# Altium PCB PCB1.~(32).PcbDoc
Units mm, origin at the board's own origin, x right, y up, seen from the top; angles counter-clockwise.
Board outline 145.29 x 144.91 mm, 2 copper layers (Top Layer, Bottom Layer); 37 components, 35 nets, 209 pads, 0 vias.
Unrouted connection lines stored in the file: 9.
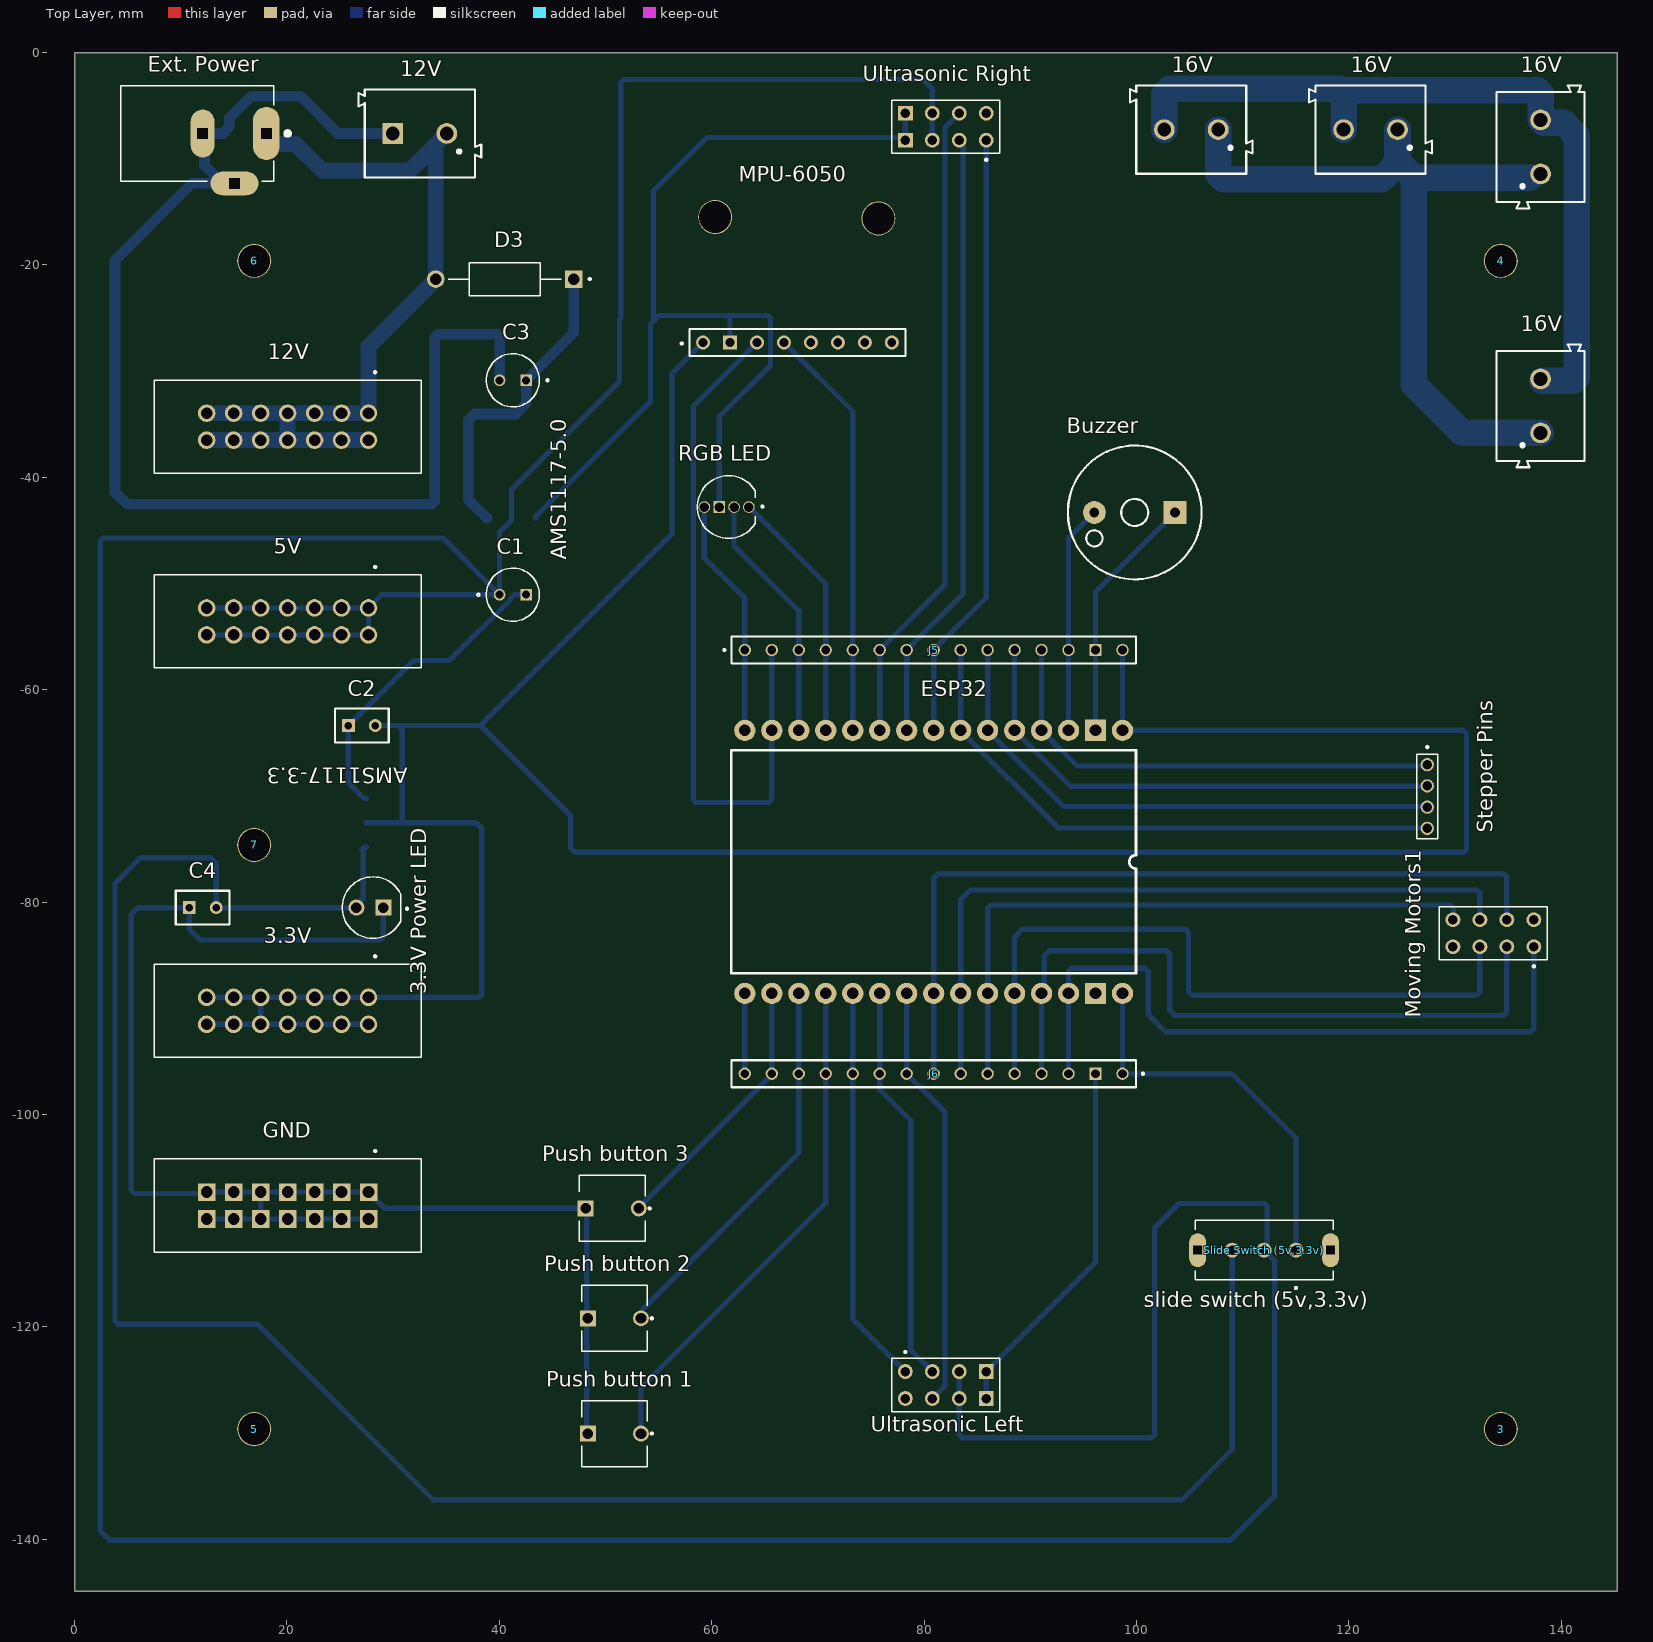
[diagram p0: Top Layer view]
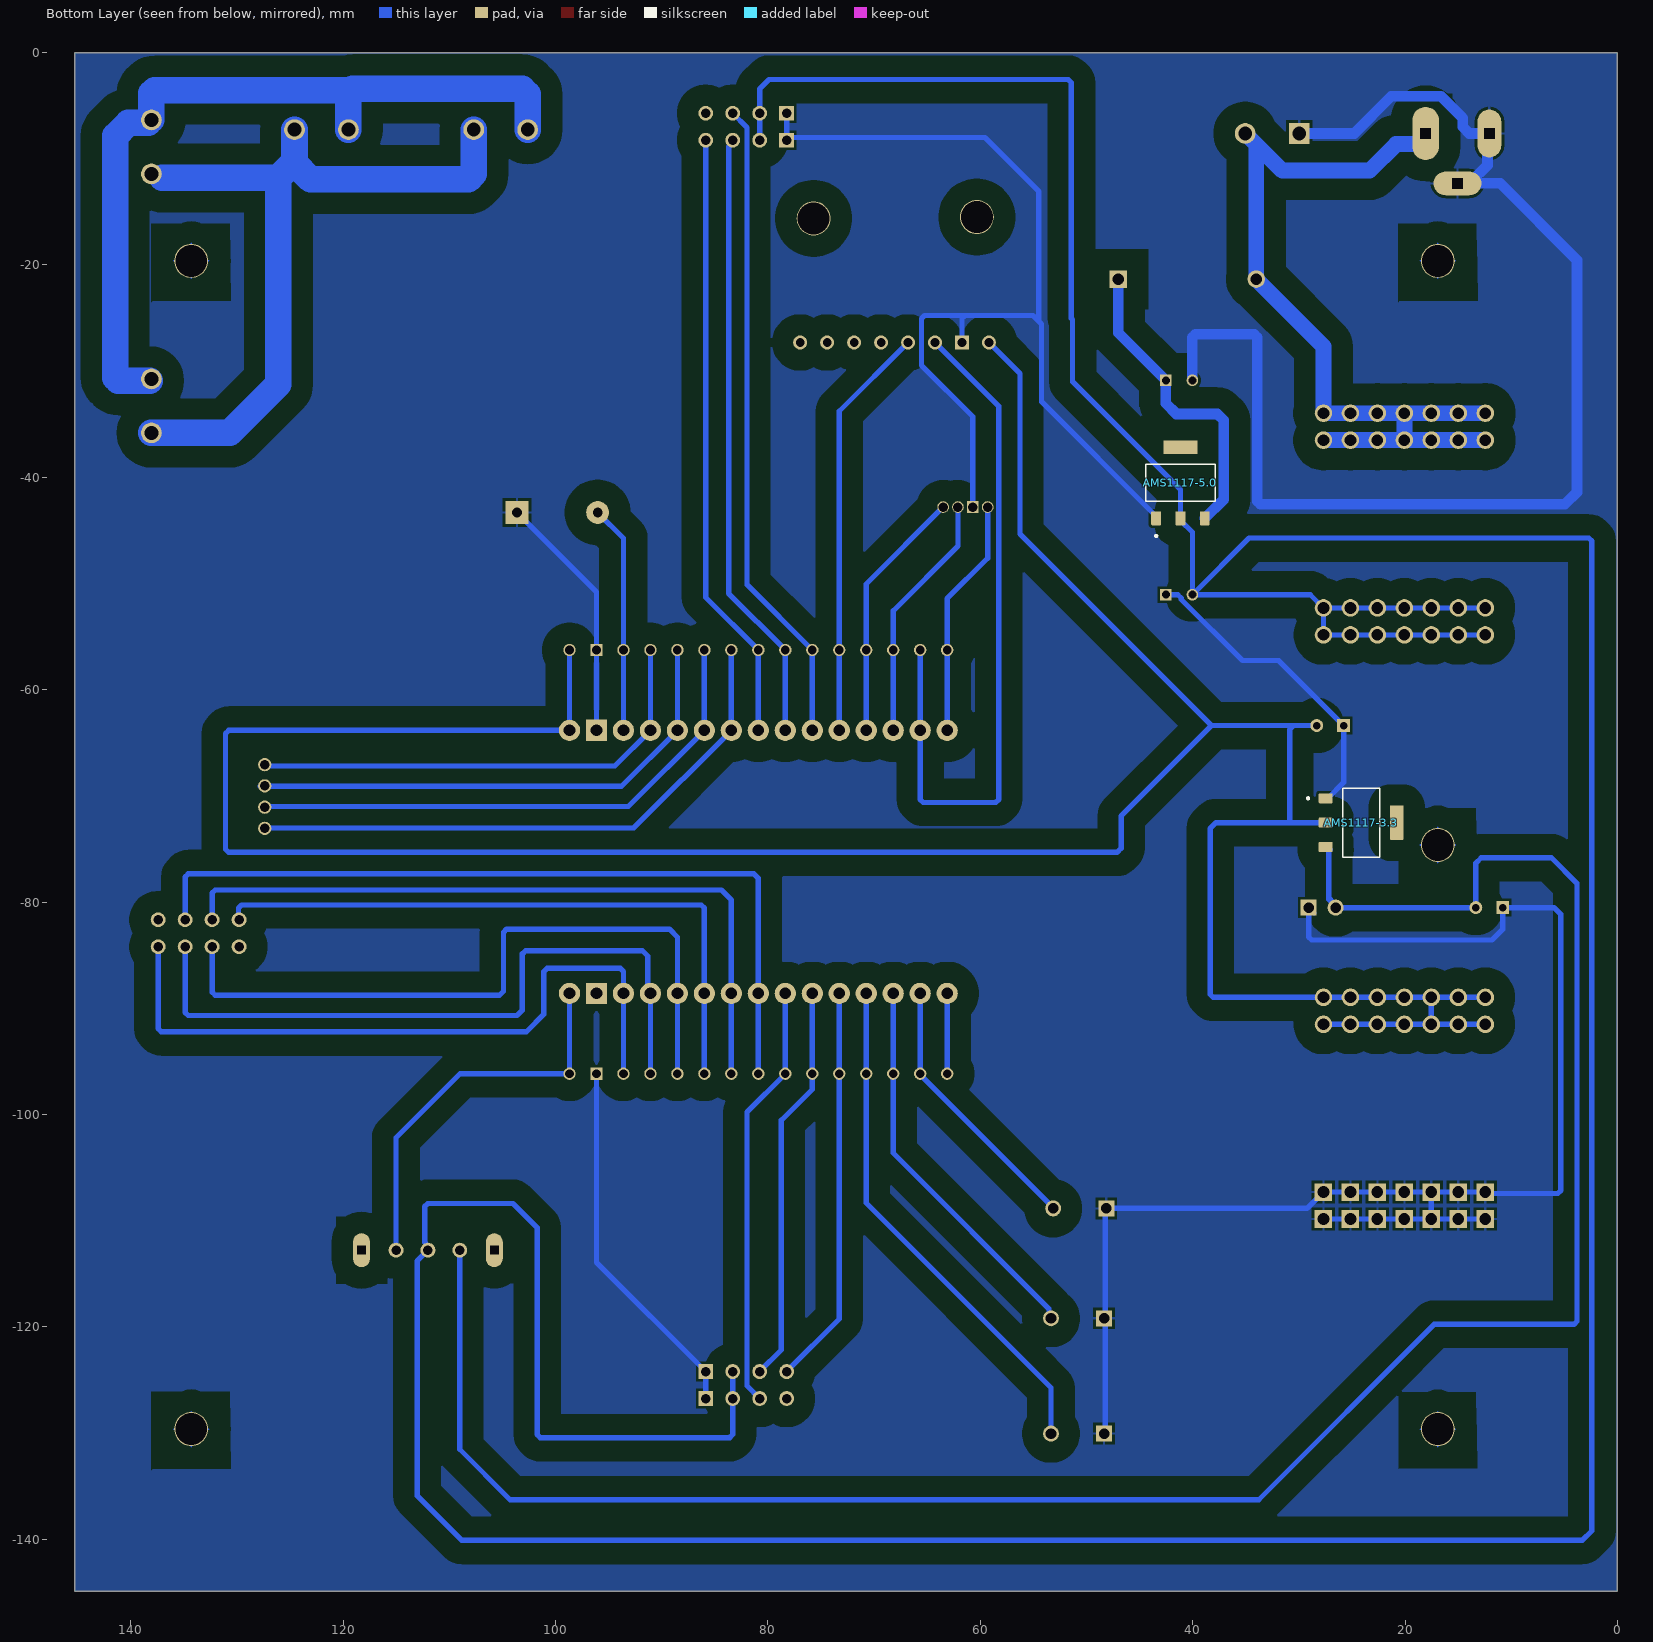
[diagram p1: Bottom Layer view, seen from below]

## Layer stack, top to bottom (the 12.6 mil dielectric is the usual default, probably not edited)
Top Solder: solder mask 0.0102, Solder Resist, Dk 3.5
Top Layer: signal copper 0.0356
Dielectric 1: dielectric 0.32, FR-4, Dk 4.8
Bottom Layer: signal copper 0.0356
Bottom Solder: solder mask 0.0102, Solder Resist, Dk 3.5

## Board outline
0,-144.907 145.288,-144.907 145.288,0 0,0

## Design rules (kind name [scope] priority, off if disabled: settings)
Clearance [All] p1: gap=0.254 ignorepadtopadclearanceinfootprint=FALSE except(0: Arc-Hole Track-Hole SMDPad-Hole THPad-Hole Via-Hole Fill-Hole Poly-Hole Region-Hole Text-Hole; 2: Arc-Poly Track-Poly SMDPad-Poly THPad-Poly)
PolygonConnect [All] p1: connectstyle=Relief reliefconductorwidth=0.254 reliefentries=4 polygonreliefangle="90 Angle" airgapwidth=0.254
RoutingLayers [All] p1: top layer_v5=FALSE bottom layer_v5=TRUE
RoutingVias [All] p1: holewidth=0.711 width=1.27 viastyle="Through Hole" minholewidth=0.711 minwidth=1.27 maxholewidth=0.711 maxwidth=1.27
SolderMaskExpansion [All] p1: expansion=0.102 istentingtop=FALSE
Width [All] p1: maxlimit=2.5 minlimit=0.254 preferedwidth=0.5
29 further rules are at their usual default settings.

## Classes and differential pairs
component class Sheet1: 3 3.3V "3.3V Power LED" 4 5 5V 6 7 12V 16V AMS1117-3.3 AMS1117-5.0 Buzzer C1 C2 C3 C4 D3 ESP32 "Ext. Power" GND J5 J6 "Moving motors" "Moving Motors1" MPU-6050 "Push button 1" "Push button 2" "Push button 3" "RGB LED" "Slide Switch (5v,3.3v)" "Stepper Pins" "Ultrasonic Left" "Ultrasonic Right"

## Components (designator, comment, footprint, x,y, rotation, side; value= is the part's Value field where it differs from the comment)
3 "Mounting Hole" PCBComponent_1 134.304,-129.619 r90 top
3.3V "3.3v pin headers block" AMPHENOL_52601-S14-4LF#1 20.066,-90.235 r180 top
"3.3V Power LED" "LED 5mm" "LED 5mm" 27.813,-80.518 r180 top
4 "Mounting Hole" PCBComponent_1 134.304,-19.619 r90 top
5 "Mounting Hole" PCBComponent_1 16.916,-129.619 r90 top
5V "5v pin headers block" AMPHENOL_52601-S14-4LF#1 20.066,-53.568 r180 top
6 "Mounting Hole" PCBComponent_1 16.916,-19.619 r90 top
7 "Mounting Hole" PCBComponent_1 16.916,-74.619 r90 top
12V "12v pin headers block" AMPHENOL_52601-S14-4LF#1 20.066,-35.235 r180 top
12V "From Buck" 691213510002#1 32.512,-7.62 r180 top
16V "From Buck" 691213510002#2 138.049,-8.89 r90 top
16V "From Buck" 691213510002#2 138.049,-33.274 r90 top
16V "From Buck" 691213510002#2 122.036,-7.26 r180 top
16V "From Buck" 691213510002#2 105.156,-7.26 r180 top
AMS1117-3.3 "AMS1117-3.3" SOT229P700X180-4N 24.13,-72.517 r180 bottom
AMS1117-5.0 "AMS1117-5.0" SOT229P700X180-4N 41.148,-40.513 r90 bottom
Buzzer "Buzzer" "Buzzer 5V" 99.832,-43.307 r180 top
C1 "CAP  33UF 50V RADIAL" "CAP  33UF 50V RADIAL"#1 41.275,-51.054 r0 top
C2 "Ceramic Capacitor 100nF" C320C 34.051,-56.373 r0 top
C3 "CAP  33UF 50V RADIAL" "CAP  33UF 50V RADIAL"#2 41.275,-30.861 r180 top
C4 "Ceramic Capacitor 100nF" C320C 19.065,-73.518 r0 top
D3 "RL207" DIOAD1300W80L670D310 40.513,-21.336 r180 top
ESP32 "ESP32DEVKITV1" ESP32DEVKITV1 81.026,-75.508 r90 top
"Ext. Power" "DC Power Jack Female Socket" "DC Power Jack Female Socket" 18.065,-7.62 r180 top
GND "GND pin headers block" AMPHENOL_52601-S14-4LF#2 20.066,-108.568 r180 top
J5 "TS-115-T-A-1" SAMTEC_TS-115-T-A-1#1 80.899,-56.261 r0 top
J6 "TS-115-T-A-1" SAMTEC_TS-115-T-A-1#2 80.899,-96.157 r180 top
"Moving Motors1" "Pin header female block 8 pin" "Pin header female block 8 pin"#1 133.604,-82.931 r180 top (schematic designator "Moving motors1")
MPU-6050 "MPU-6050" MPU-6050 57.658,-28.829 r90 top
"Push button 1" "FSM8JRT" TE_FSM8JRT 53.34,-130.048 r180 top
"Push button 2" "FSM8JRT" TE_FSM8JRT 53.34,-119.189 r180 top
"Push button 3" "FSM8JRT" TE_FSM8JRT 53.137,-108.839 r180 top
"RGB LED" "common cathode" "LED RGB 5mm" 61.595,-42.799 r180 top
"Slide Switch (5v,3.3v)" "slide switch (5v,3.3v)" "Slide switch" 112.014,-112.776 r180 top
"Stepper Pins" "Pin hreader 4 pins" "Pin hreader 4 pins" 127.381,-67.056 r270 top
"Ultrasonic Left" "Pin header female block 8 pin" "Pin header female block 8 pin"#2 82.042,-125.476 r0 top
"Ultrasonic Right" "Pin header female block 8 pin" "Pin header female block 8 pin"#2 82.042,-6.985 r180 top

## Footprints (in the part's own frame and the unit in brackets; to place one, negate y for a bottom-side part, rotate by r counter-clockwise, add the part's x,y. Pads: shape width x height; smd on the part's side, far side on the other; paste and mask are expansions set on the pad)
691213510002#1 [mm]
  round 1.95 hole 1.3: 1(-2.54,0)
  rect 1.95x1.95 hole 1.3: 2(2.54,0)
  silkscreen extent -5.78,-4.15 5.78,4.15, body extent -5.68,-3.94 5.68,4.16, height 10
691213510002#2 [mm]
  round 1.95 hole 1.3: 1(-2.54,0) 2(2.54,0)
  silkscreen extent -5.78,-4.15 5.78,4.15, body extent -5.68,-3.94 5.68,4.16, height 10
AMPHENOL_52601-S14-4LF#1 [mm]
  round 1.65 hole 1.1: 1(-7.62,-1.27) 2(-7.62,1.27) 3(-5.08,-1.27) 4(-5.08,1.27) 5(-2.54,-1.27) 6(-2.54,1.27) 7(0,-1.27) 8(0,1.27) 9(2.54,-1.27) 10(2.54,1.27) 11(5.08,-1.27) 12(5.08,1.27) 13(7.62,-1.27) 14(7.62,1.27)
  silkscreen extent -12.57,-5.23 12.57,4.38, body extent -12.57,-4.38 12.57,4.38, height 9.53
AMPHENOL_52601-S14-4LF#2 [mm]
  rect 1.65x1.65 hole 1.1: 1(-7.62,-1.27) 2(-7.62,1.27) 3(-5.08,-1.27) 4(-5.08,1.27) 5(-2.54,-1.27) 6(-2.54,1.27) 7(0,-1.27) 8(0,1.27) 9(2.54,-1.27) 10(2.54,1.27) 11(5.08,-1.27) 12(5.08,1.27) 13(7.62,-1.27) 14(7.62,1.27)
  silkscreen extent -12.57,-5.23 12.57,4.38, body extent -12.57,-4.38 12.57,4.38, height 9.53
"Buzzer 5V" [mil]
  rect 85x85 hole 36: NEG(-149.61,0)
  round 85 hole 36: POS(149.61,0)
  silkscreen extent -248,-248 248,248, body extent -236,-236 236,236, height 394
C320C [mm]
  rect 1.21x1.21 hole 0.71: 1(-8.27,-7)
  round 1.21 hole 0.71: 2(-5.73,-7)
  silkscreen extent -9.54,-8.59 -4.46,-5.41, body extent -9.53,-8.57 -4.45,-5.4, height 7.1
"CAP  33UF 50V RADIAL"#1 [mm]
  rect 1.1x1.1 hole 0.75: N(1.25,0)
  round 1.1 hole 0.75: P(-1.25,0)
  silkscreen extent -3.35,-2.5 2.5,2.5, body extent -2.49,-2.5 2.5,2.5, height 11
"CAP  33UF 50V RADIAL"#2 [mm]
  round 1.1 hole 0.75: N(1.25,0)
  rect 1.1x1.1 hole 0.75: P(-1.25,0)
  silkscreen extent -3.35,-2.5 2.5,2.5, body extent -2.49,-2.5 2.5,2.5, height 11
"DC Power Jack Female Socket" [mm]
  oval 2.5x5 hole 1 square: 1(0,0)
  oval 2.25x4.5 hole 1 square: 2(6,0)
  oval 4.5x2.25 hole 1 square: 3(3,4.7)
  silkscreen extent -2.2,-4.5 13.7,4.5, body extent -0.7,-4.5 13.7,4.9, height 11
DIOAD1300W80L670D310 [mm]
  round 1.65 hole 1.1: A(6.5,0)
  rect 1.65x1.65 hole 1.1: C(-6.5,0)
  silkscreen extent -8.1,-1.55 5.32,1.55, body extent -6.9,-1.95 6.9,1.65, height 3.6
ESP32DEVKITV1 [mm]
  round 2 hole 1.1: 1(11.684,-17.653) 3(11.684,-12.573) 4(11.684,-10.033) 5(11.684,-7.493) 6(11.684,-4.953) 7(11.684,-2.413) 8(11.684,0.127) 9(11.684,2.667) 10(11.684,5.207) 11(11.684,7.747) 12(11.684,10.287) 13(11.684,12.827) 14(11.684,15.367) 15(11.684,17.907) 16(-13.086,17.907) 17(-13.086,15.367) 18(-13.086,12.827) 19(-13.086,10.287) 20(-13.086,7.747) 21(-13.086,5.207) 22(-13.086,2.667) 23(-13.086,0.127) 24(-13.086,-2.413) 25(-13.086,-4.953) 26(-13.086,-7.493) 27(-13.086,-10.033) 28(-13.086,-12.573) 30(-13.086,-17.653)
  rect 2x2 hole 1.1: 2(11.684,-15.113) 29(-13.086,-15.113)
  silkscreen extent -11.2,-18.92 9.79,19.18, body extent -15.13,-28.49 13.86,24.48, height 8.36
"LED 5mm" [mm]
  round 1.508 hole 1: A(1.27,0)
  rect 1.508x1.508 hole 1: C(-1.27,0)
  silkscreen extent -3.6,-2.9 2.6,2.9, body extent -2.88,-2.9 2.51,2.9, height 12.1
"LED RGB 5mm" [mm]
  round 1.1 hole 0.9: 1(-1.905,0) 2(-0.508,0) 4(2.286,0)
  rect 1.1x1.1 hole 0.9: 3(0.889,0)
  silkscreen extent -3.27,-2.95 2.95,2.95, body extent -2.47,-3.05 2.98,2.84, height 9.6
MPU-6050 [mil]
  round 52 hole 32: 01(60,-60) 03(60,-260) 04(60,-360) 05(60,-460) 06(60,-560) 07(60,-660) 08(60,-760)
  rect 52x52 hole 32: 02(60,-160)
  round 125.98 hole 118.11: ""(520,-710) ""(525,-105)
  silkscreen extent 10,-810 110,23, body extent 15,-811 615,-9, height 612
PCBComponent_1 [mm]
  round 3.2 hole 3: ""(0,0)
  Bottom Layer lines w0.15: 0,1.649 0,-1.651 ; -1.651,0 1.649,0
"Pin header female block 8 pin"#1 [mm]
  round 1.398 hole 0.89: 1(-3.81,1.27) 2(-1.27,1.27) 3(1.27,1.27) 4(3.81,1.27) 5(-3.81,-1.27) 6(-1.27,-1.27) 7(1.27,-1.27) 8(3.81,-1.27)
  silkscreen extent -5.08,-2.52 5.08,3.21, body extent -5.08,-2.51 5.08,2.51, height 6.22
"Pin header female block 8 pin"#2 [mm]
  round 1.398 hole 0.89: 1(-3.81,1.27) 2(-1.27,1.27) 3(1.27,1.27) 5(-3.81,-1.27) 6(-1.27,-1.27) 7(1.27,-1.27)
  rect 1.398x1.398 hole 0.89: 4(3.81,1.27) 8(3.81,-1.27)
  silkscreen extent -5.08,-2.52 5.08,3.21, body extent -5.08,-2.51 5.08,2.51, height 6.22
"Pin hreader 4 pins" [mm]
  round 1.25 hole 0.9: 1(0,0) 2(2,0) 3(4,0) 4(6,0)
  silkscreen extent -1.75,-1 7,1, body extent -1.01,-1.02 6.98,0.98, height 5.78
SAMTEC_TS-115-T-A-1#1 [mil]
  round 45.78 hole 32: 01(-700,0) 02(-600,0) 03(-500,0) 04(-400,0) 05(-300,0) 06(-200,0) 07(-100,0) 08(0,0) 09(100,0) 10(200,0) 11(300,0) 12(400,0) 13(500,0) 15(700,0)
  rect 45.78x45.78 hole 32: 14(600,0)
  silkscreen extent -780,-50 750,50, body extent -754,-50 754,50, height 326
SAMTEC_TS-115-T-A-1#2 [mil]
  round 45.78 hole 32: 01(-700,0) 03(-500,0) 04(-400,0) 05(-300,0) 06(-200,0) 07(-100,0) 08(0,0) 09(100,0) 10(200,0) 11(300,0) 12(400,0) 13(500,0) 14(600,0) 15(700,0)
  rect 45.78x45.78 hole 32: 02(-600,0)
  silkscreen extent -780,-50 750,50, body extent -754,-50 754,50, height 326
"Slide switch" [mm]
  round 1.408 hole 0.9: 1(-3,0) 2(0,0) 3(3,0)
  oval 1.6x3.2 hole 0.8 square: SH1(-6.25,0) SH2(6.25,0)
  silkscreen extent -6.5,-2.8 6.5,3.66, body extent -6.5,-5.8 6.5,2.8, height 6
SOT229P700X180-4N [mm]
  rrect15% 1.31x0.93 smd: 1(-3.345,2.29) 2(-3.345,0) 3(-3.345,-2.29)
  rrect15% 1.31x3.24 smd: 4(3.345,0)
  silkscreen extent -5.1,-3.25 1.75,3.25, body extent -3.5,-3.25 3.5,3.25, height 1.8
TE_FSM8JRT [mil]
  round 59 hole 39: 1(0,0)
  rect 59x59 hole 39: 2(197,0)
  silkscreen extent -44,-122 221,122, body extent -22,-122 222,122, height 372

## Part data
3.3V 5V 12V GND: library part 52601-S14-4LF, Package=None
"3.3V Power LED": "Red 623nm LED Indication - Discrete 1.9V Radial", Package=None
12V 16V 16V 16V 16V: library part "Terminal Block", "2 Position Wire to Board Terminal Block Horizontal with Board 0.200 (5.08mm) Through Hole", Package=None
AMS1117-3.3 AMS1117-5.0 J5 J6 "Moving Motors1" "Stepper Pins" "Ultrasonic Left" "Ultrasonic Right": Package=None
Buzzer: library part "Buzzer 5V", "BUZZER 2.3KHZ 4-6VDC", Package=None
C1 C3: "NHG-A", Package=None
C2 C4: "0.1ÂµF Â±20% 50V Ceramic Capacitor Z5U Radial", Package="Radial KEMET"
D3: "Semiconductors and Actives, Power Diodes, Discretes (diodes, transistors, thyristors ...), Diodes", Package=None
"Ext. Power": "2.0 mm Center Pin, 2.5 A, Right Angle, Through Hole, Dc Power Jack Connector", Package=None
"Push button 1" "Push button 2" "Push button 3": "Tactile Switches PUSHBUTTON SWITCH TACT", Package=None
"RGB LED": library part "LED RGB 5mm", Package=None
"Slide Switch (5v,3.3v)": library part "Slide switch", Package=None

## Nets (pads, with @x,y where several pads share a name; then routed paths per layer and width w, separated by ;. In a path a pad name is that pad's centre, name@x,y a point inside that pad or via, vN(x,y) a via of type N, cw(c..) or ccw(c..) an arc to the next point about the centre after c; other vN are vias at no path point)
3.3V: 3.3V.1 3.3V.2 3.3V.3 3.3V.4 3.3V.5 3.3V.6 3.3V.7 3.3V.8 3.3V.9 3.3V.10 3.3V.11 3.3V.12 3.3V.13 3.3V.14 AMS1117-3.3.2 C2.2 ESP32.1 J5.15 MPU-6050.01 | length 285.1
  Bottom Layer w0.5: 3.3V.14 3.3V.12 3.3V.10 ; 3.3V.13 3.3V.11 3.3V.9 ; AMS1117-3.3.2 30.861,-72.517 ; 3.3V.2 3.3V.4 3.3V.6 3.3V.8 3.3V.10 ; C2.2 30.48,-63.373 ; MPU-6050.01 56.261,-30.226 56.261,-45.339 38.227,-63.373 ; J5.15 ESP32.1 130.771,-63.824 131.064,-64.117 131.064,-75.018 130.771,-75.311 47.117,-75.311 46.736,-74.93 46.736,-71.882 38.227,-63.373 ; 3.3V.10 3.3V.9 ; 3.3V.9 3.3V.7 3.3V.5 3.3V.3 3.3V.1 38.061,-88.965 38.354,-88.672 38.354,-73.064 37.807,-72.517 30.861,-72.517 ; 30.48,-63.373 30.861,-63.754 30.861,-72.517 ; 30.48,-63.373 38.227,-63.373
+5: 5V.1 5V.2 5V.3 5V.4 5V.5 5V.6 5V.7 5V.8 5V.9 5V.10 5V.11 5V.12 5V.13 5V.14 "Slide Switch (5v,3.3v).2" "Ultrasonic Left.3" "Ultrasonic Left.7" "Ultrasonic Right.3" "Ultrasonic Right.7" AMS1117-5.0.2 C1.P | length 462.8
  Bottom Layer w0.5: 5V.14 5V.12 5V.10 5V.8 5V.6 5V.4 5V.2 5V.1 ; 5V.13 5V.11 5V.9 5V.7 5V.5 5V.3 5V.1 ; 80.772,-8.255 80.772,-5.715 80.772,-3.429 79.883,-2.54 51.728,-2.54 51.435,-2.833 51.435,-25.019 51.308,-25.146 51.308,-30.988 41.148,-41.148 AMS1117-5.0.2 41.148,-44.048 40.025,-45.171 C1.P ; 83.312,-124.206 83.312,-126.746 83.312,-130.136 83.605,-130.429 101.434,-130.429 101.727,-130.136 101.727,-110.65 103.998,-108.379 112.023,-108.379 112.316,-108.672 112.316,-112.029 112.188,-112.157 112.188,-112.602 112.014,-112.776 113.03,-113.792 113.03,-135.89 108.839,-140.081 3.302,-140.081 2.413,-139.192 2.413,-46.013 2.706,-45.72 34.691,-45.72 C1.P ; 5V.1 28.93,-51.054 C1.P
+12: 12V.1 12V.2@27.686,-36.505 12V.3 12V.4 12V.5 12V.6 12V.7 12V.8 12V.9 12V.10 12V.11 12V.12 12V.13 12V.14 "Ext. Power.1" D3.A | length 82.3
  Bottom Layer w0.5: 18.065,-7.62 18.065,-7.696 18.989,-8.62 ; 34.013,-9.021 35.052,-7.981 12V.1@35.052,-7.62
  Bottom Layer w1.5: 12V.14 12V.12 12V.10 12V.8 ; 12V.13 12V.11 12V.9 12V.7 ; 18.989,-8.62 20.845,-8.62 23.345,-11.12 31.552,-11.12 12V.1@35.052,-7.62 ; 12V.2@27.686,-36.505 12V.4 12V.6 12V.8 ; D3.A 27.686,-27.663 27.686,-33.965 12V.3 12V.5 12V.7 ; D3.A@34.013,-21.313 34.013,-9.021 ; 12V.8 12V.7
GND: 12V.2@29.972,-7.62 "3.3V Power LED.C" "Ext. Power.2" "Ext. Power.3" "Push button 1.2" "Push button 2.2" "Push button 3.2" "RGB LED.3" "Ultrasonic Left.4" "Ultrasonic Left.8" "Ultrasonic Right.4" "Ultrasonic Right.8" AMS1117-3.3.1 AMS1117-5.0.1 Buzzer.NEG C1.N C2.1 C3.N C4.1 ESP32.2 ESP32.29 GND.1 GND.2 GND.3 GND.4 GND.5 GND.6 GND.7 GND.8 GND.9 GND.10 GND.11 GND.12 GND.13 GND.14 J5.14 J6.02 MPU-6050.02 | length 443.8
  Bottom Layer w0.5: 12.065,-7.62 12.24,-7.795 ; GND.14 GND.12 GND.10 ; 13.94,-12.32 15.065,-12.32 ; AMS1117-3.3.1 27.285,-70.227 25.781,-68.723 C2.1 31.9,-57.254 35.315,-57.254 41.079,-51.491 41.079,-51.377 41.402,-51.054 C1.N ; GND.2 GND.4 GND.6 GND.8 GND.10 ; 28.579,-81.022 29.083,-80.518 29.083,-83.273 28.79,-83.566 11.811,-83.566 10.795,-82.55 C4.1 5.969,-80.518 5.334,-81.153 5.334,-107.149 5.627,-107.442 12.302,-107.442 GND.13 GND.11 GND.9 ; 33.616,-42.545 33.909,-42.252 ; 33.909,-26.836 34.202,-26.543 ; 39.732,-26.543 40.025,-26.836 ; AMS1117-5.0.1 43.438,-43.668 54.229,-32.877 54.229,-25.566 54.483,-25.312 ; 48.336,-130.048 48.235,-129.946 48.235,-108.941 48.133,-108.839 29.227,-108.839 GND.1 GND.3 GND.5 GND.7 GND.9 ; 60.706,-42.799 60.706,-34.29 65.532,-29.464 65.532,-25.058 65.239,-24.765 61.722,-24.765 61.468,-24.765 ; MPU-6050.02 61.722,-25.019 61.595,-24.892 61.468,-24.765 ; 78.232,-5.715 78.232,-8.255 77.978,-8.001 59.563,-8.001 54.483,-13.081 54.483,-25.312 ; 85.852,-126.746 85.852,-124.206 96.139,-113.919 J6.02 ; ESP32.2 J5.14 96.139,-50.8 Buzzer.NEG ; GND.10 GND.9 ; 54.483,-25.312 55.03,-24.765 61.468,-24.765
  Bottom Layer w1: 12.065,-7.62 13.94,-7.62 14.565,-6.995 14.565,-6.17 16.615,-4.12 21.295,-4.12 24.795,-7.62 12V.2@29.972,-7.62 ; 12.24,-7.795 12.24,-10.62 13.94,-12.32 11.048,-12.32 3.81,-19.558 3.81,-41.402 4.953,-42.545 33.616,-42.545 ; 33.909,-42.252 33.909,-26.836 ; 34.202,-26.543 39.732,-26.543 ; C3.N 40.025,-26.836
"Net3.3V Power LED_A": "3.3V Power LED.A" "Slide Switch (5v,3.3v).3" AMS1117-3.3.3 C4.2 | length 210
  Bottom Layer w0.5: 26.543,-80.518 26.543,-80.245 27.051,-79.737 ; AMS1117-3.3.3@27.051,-75.041 27.285,-74.807 AMS1117-3.3.3 27.393,-74.807 27.178,-75.022 27.178,-79.737 26.67,-80.245 26.67,-80.518 C4.2 13.335,-76.327 12.827,-75.819 6.223,-75.819 3.81,-78.232 3.81,-119.468 4.103,-119.761 17.272,-119.761 33.782,-136.271 104.267,-136.271 109.014,-131.524 109.014,-112.776
Net16V_1: 16V.1 | length 72.4
  Bottom Layer w0.5: 137.031,-11.811 137.135,-11.707 137.772,-11.707 16V.1@138.049,-11.43
  Bottom Layer w2.5: 16V.1@107.696,-7.26 107.696,-11.43 108.204,-11.938 123.053,-11.938 124.576,-10.415 ; 16V.1@124.576,-7.26 124.576,-10.276 126.111,-11.811 ; 137.031,-11.811 126.111,-11.811 ; 16V.1@138.049,-35.814 130.683,-35.814 126.111,-31.242 126.111,-11.811
Net16V_2: 16V.2 | length 75.7
  Bottom Layer w0.5: 102.616,-3.937 103.124,-3.429 ; 119.077,-3.429 119.496,-3.849 119.789,-3.556 ; 137.756,-3.556 138.049,-3.849 ; 16V.2@138.049,-30.734 16V.2@138.21,-30.895 ; 16V.2@138.049,-6.35 16V.2@138.326,-6.627 ; 141.151,-30.895 141.444,-30.602
  Bottom Layer w2.5: 16V.2@102.616,-7.26 102.616,-3.937 ; 103.124,-3.429 119.077,-3.429 ; 16V.2@119.496,-7.26 119.496,-3.849 ; 119.789,-3.556 137.756,-3.556 ; 16V.2@138.049,-6.35 138.049,-3.849 ; 16V.2@138.21,-30.895 141.151,-30.895 ; 16V.2@138.326,-6.627 140.231,-6.627 141.444,-7.84 141.444,-30.602
NetAMS1117-5.0_3: AMS1117-5.0.3 C3.P D3.C | length 29.6
  Bottom Layer w1: AMS1117-5.0.3 37.084,-42.084 37.084,-34.622 37.67,-34.036 41.529,-34.036 42.525,-33.04 C3.P 47.013,-26.373 D3.C
NetBuzzer_POS: Buzzer.POS ESP32.3 J5.13 | length 21.5
  Bottom Layer w0.5: ESP32.3 J5.13 93.599,-45.74 Buzzer.POS
NetESP32_4: "Stepper Pins.1" ESP32.4 J5.12 | length 45.3
  Bottom Layer w0.5: J5.12 ESP32.4 94.418,-67.183 127.254,-67.183 127.381,-67.056
NetESP32_5: "Stepper Pins.2" ESP32.5 J5.11 | length 49
  Bottom Layer w0.5: J5.11 ESP32.5 93.783,-69.088 127.797,-69.088
NetESP32_6: "Stepper Pins.3" ESP32.6 J5.10 | length 52
  Bottom Layer w0.5: J5.10 ESP32.6 93.148,-70.993 127.449,-70.993
NetESP32_7: "Stepper Pins.4" ESP32.7 J5.09 | length 55.6
  Bottom Layer w0.5: J5.09 ESP32.7 92.64,-73.025 127.64,-73.025
NetESP32_8: "Ultrasonic Right.1" ESP32.8 J5.08 | length 57.6
  Bottom Layer w0.5: ESP32.8 J5.08 85.852,-51.308 85.852,-8.255
NetESP32_9: "Ultrasonic Right.2" ESP32.9 J5.07 | length 57.9
  Bottom Layer w0.5: ESP32.9 J5.07 83.693,-50.927 83.693,-8.879 83.312,-8.498 83.312,-8.255
NetESP32_10: "Ultrasonic Right.6" ESP32.10 J5.06 | length 61.2
  Bottom Layer w0.5: ESP32.10 J5.06 81.975,-50.105 81.975,-7.052 83.312,-5.715
NetESP32_11: ESP32.11 J5.05 MPU-6050.04 | length 39.2
  Bottom Layer w0.5: MPU-6050.04 73.279,-33.782 ESP32.11
NetESP32_12: "RGB LED.1" ESP32.12 J5.04 | length 24
  Bottom Layer w0.5: 63.5,-42.799 70.739,-50.038 J5.04 ESP32.12
NetESP32_13: "RGB LED.2" ESP32.13 J5.03 | length 23.6
  Bottom Layer w0.5: 62.103,-42.799 62.103,-46.474 68.199,-52.57 J5.03 ESP32.13
NetESP32_14: ESP32.14 J5.02 MPU-6050.03 | length 67.2
  Bottom Layer w0.5: MPU-6050.03 58.255,-33.312 58.255,-70.319 58.548,-70.612 65.366,-70.612 65.659,-70.319 ESP32.14 J5.02
NetESP32_15: "RGB LED.4" ESP32.15 J5.01 | length 22.6
  Bottom Layer w0.5: 59.309,-42.799 59.309,-47.617 63.119,-51.427 J5.01 ESP32.15
NetESP32_16: ESP32.16 J6.15 | length 7.6
  Bottom Layer w0.5: J6.15 ESP32.16
NetESP32_17: "Push button 3.1" ESP32.17 J6.14 | length 25.4
  Bottom Layer w0.5: 53.137,-108.839 53.137,-108.759 65.659,-96.237 J6.14 ESP32.17
NetESP32_18: "Push button 2.1" ESP32.18 J6.13 | length 36.8
  Bottom Layer w0.5: 53.34,-119.189 53.531,-118.998 53.531,-118.3 68.199,-103.632 J6.13 ESP32.18
NetESP32_19: "Push button 1.1" ESP32.19 J6.12 | length 48.7
  Bottom Layer w0.5: 53.34,-130.048 53.34,-125.73 70.739,-108.331 J6.12 ESP32.19
NetESP32_20: "Ultrasonic Left.1" ESP32.20 J6.11 | length 37.7
  Bottom Layer w0.5: ESP32.20 73.279,-119.253 78.232,-124.206
NetESP32_21: "Ultrasonic Left.2" ESP32.21 J6.10 | length 37.7
  Bottom Layer w0.5: ESP32.21 J6.10 75.819,-97.631 78.74,-100.552 78.74,-122.174 80.772,-124.206
NetESP32_22: "Ultrasonic Left.6" ESP32.22 J6.09 | length 40.1
  Bottom Layer w0.5: ESP32.22 J6.09 81.975,-99.773 81.975,-125.543 80.772,-126.746
NetESP32_23: "Moving Motors1.6" ESP32.23 J6.08 | length 76.7
  Bottom Layer w0.5: J6.08 ESP32.23 80.899,-77.763 81.319,-77.343 134.581,-77.343 134.874,-77.636 134.874,-81.661
NetESP32_24: "Moving Motors1.7" ESP32.24 J6.07 | length 68.3
  Bottom Layer w0.5: J6.07 ESP32.24 83.439,-79.795 84.367,-78.867 132.041,-78.867 132.334,-79.16 132.334,-81.661
NetESP32_25: "Moving Motors1.8" ESP32.25 J6.06 | length 60.8
  Bottom Layer w0.5: J6.06 ESP32.25 85.979,-80.557 86.272,-80.264 129.556,-80.264 129.849,-80.557 129.849,-81.606 129.794,-81.661
NetESP32_26: "Moving Motors1.3" ESP32.26 J6.05 | length 67.2
  Bottom Layer w0.5: J6.05 ESP32.26 88.519,-83.312 89.281,-82.55 104.609,-82.55 104.902,-82.843 104.902,-88.392 105.283,-88.773 132.041,-88.773 132.334,-88.48 132.334,-84.201
NetESP32_27: "Moving Motors1.2" ESP32.27 J6.04 | length 66.9
  Bottom Layer w0.5: J6.04 ESP32.27 91.313,-88.34 91.313,-85.09 91.821,-84.582 102.831,-84.582 103.124,-84.875 103.124,-90.17 103.632,-90.678 134.581,-90.678 134.874,-90.385 134.874,-84.201
NetESP32_28: "Moving Motors1.1" ESP32.28 J6.03 | length 66.2
  Bottom Layer w0.5: J6.03 93.599,-86.526 93.892,-86.233 100.799,-86.233 101.092,-86.526 101.092,-90.551 102.743,-92.202 137.121,-92.202 137.414,-91.909 137.414,-84.201
NetESP32_30: "Slide Switch (5v,3.3v).1" ESP32.30 J6.01 | length 37
  Bottom Layer w0.5: ESP32.30 J6.01 108.984,-96.157 115.014,-102.187 115.014,-112.776
pads on no net: 3. 4. 5. 6. 7. "Moving Motors1.4" "Moving Motors1.5" "Slide Switch (5v,3.3v).SH1" "Slide Switch (5v,3.3v).SH2" "Ultrasonic Left.5" "Ultrasonic Right.5" AMS1117-3.3.4 AMS1117-5.0.4 MPU-6050. MPU-6050.05 MPU-6050.06 MPU-6050.07 MPU-6050.08

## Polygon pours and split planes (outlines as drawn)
GND on Bottom Layer "GND_L02_P000" (solid, pour order 0): 0,-144.907 145.288,-144.907 145.288,0 0,0

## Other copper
Bottom Layer:
  pour cut-out: 13.295,-16.129 20.661,-16.129 20.661,-23.495 20.534,-23.368 13.168,-23.368
  pour cut-out: 13.295,-71.129 20.661,-71.129 20.661,-78.495 20.534,-78.368 13.168,-78.368
  pour cut-out: 13.295,-126.129 20.661,-126.129 20.661,-133.495 20.534,-133.368 13.168,-133.368
  pour cut-out: 130.683,-126.129 138.049,-126.129 138.049,-133.495 137.922,-133.368 130.556,-133.368
  pour cut-out: 130.683,-16.129 138.049,-16.129 138.049,-23.495 137.922,-23.368 130.556,-23.368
